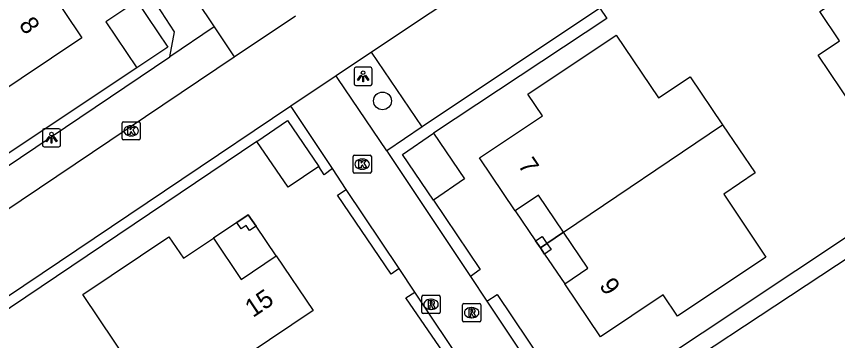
# Model space of a CAD drawing. Extents: x 158797 to 159887, y 384318 to 385255.
# Drawn here: x 159048.69 to 159093.85, y 384674.82 to 384692.68 of the extents above; entities that cross this region are included whole.
import ezdxf

# ---------------------------------------------------------------- set-up
doc = ezdxf.new("R2010")
doc.units = 0
for name, color, linetype in [('IMGEO_Boom', 7, 'Continuous'), ('IMGEO_Haag', 7, 'Continuous'), ('IMGEO_Kolk', 7, 'Continuous'), ('IMGEO_Lichtpunt', 7, 'Continuous'), ('IMGEO_Pand', 7, 'Continuous'), ('IMGEO_Pand_nummerreeks', 7, 'Continuous'), ('IMGEO_Pand_overbouw', 7, 'Continuous'), ('IMGEO_Parkeervlak_open', 7, 'Continuous'), ('IMGEO_Rijbaan_lokaal_open', 7, 'Continuous'), ('IMGEO_Rioolput', 7, 'Continuous'), ('IMGEO_Voetpad_open', 7, 'Continuous')]:
    doc.layers.add(name, color=color, linetype=linetype)

msp = doc.modelspace()

# ---------------------------------------------------------------- linework, layer by layer
at = {"layer": 'IMGEO_Boom'}
msp.add_circle((159068.824, 384688.021), 0.489, dxfattribs=at)
at = {"layer": 'IMGEO_Haag'}
for points in [[(159080.775, 384693.133), (159081.167, 384692.563), (159071.631, 384686.237)], [(159055.316, 384689.846), (159042.109, 384681.044)], [(159071.015, 384686.602), (159069.058, 384685.263)], [(159061.91, 384685.784), (159047.504, 384676.068), (159047.185, 384676.54)], [(159066.072, 384684.293), (159065.616, 384683.953), (159065.322, 384684.416)], [(159081.043, 384672.126), (159081.247, 384671.812), (159096.708, 384682.114), (159098.87, 384679.188), (159107.236, 384684.664), (159107.906, 384683.665)], [(159069.74, 384678.786), (159069.295, 384678.477), (159066.351, 384682.826), (159066.834, 384683.149)], [(159071.628, 384682.562), (159074.194, 384678.736), (159073.658, 384678.352)], [(159079.482, 384669.508), (159096.312, 384680.64), (159097.742, 384678.578)], [(159073.399, 384673.289), (159072.96, 384673.002), (159070.111, 384677.172), (159070.61, 384677.479)], [(159074.561, 384676.996), (159075.131, 384677.353), (159077.683, 384673.558)]]:
    msp.add_lwpolyline(points, dxfattribs=at)
at = {"layer": 'IMGEO_Kolk'}
for p, q in [((159054.503, 384685.948), (159054.503, 384686.8)), ((159054.578, 384686.874), (159055.43, 384686.874)), ((159054.991, 384686.654), (159055.016, 384686.654)), ((159055.504, 384686.8), (159055.504, 384685.948)), ((159055.014, 384686.094), (159054.989, 384686.094)), ((159055.43, 384685.874), (159054.578, 384685.874)), ((159067.211, 384684.108), (159067.211, 384684.96)), ((159067.286, 384685.034), (159068.138, 384685.034)), ((159067.699, 384684.814), (159067.724, 384684.814)), ((159068.212, 384684.96), (159068.212, 384684.108)), ((159068.138, 384684.034), (159067.286, 384684.034)), ((159067.722, 384684.254), (159067.697, 384684.254))]:
    msp.add_line(p, q, dxfattribs=at)
for points in [[(159054.503, 384685.948), (159054.503, 384686.8)], [(159054.578, 384686.874), (159055.43, 384686.874)], [(159054.824, 384686.574), (159054.947, 384686.574), (159054.947, 384686.423), (159055.077, 384686.574), (159055.241, 384686.574), (159055.095, 384686.423), (159055.248, 384686.174), (159055.096, 384686.174), (159055.011, 384686.338), (159054.947, 384686.271), (159054.947, 384686.174), (159054.824, 384686.174), (159054.824, 384686.574)], [(159055.504, 384686.8), (159055.504, 384685.948)], [(159055.43, 384685.874), (159054.578, 384685.874)], [(159067.211, 384684.108), (159067.211, 384684.96)], [(159067.286, 384685.034), (159068.138, 384685.034)], [(159067.532, 384684.734), (159067.655, 384684.734), (159067.655, 384684.583), (159067.785, 384684.734), (159067.949, 384684.734), (159067.803, 384684.583), (159067.956, 384684.334), (159067.804, 384684.334), (159067.719, 384684.498), (159067.655, 384684.431), (159067.655, 384684.334), (159067.532, 384684.334), (159067.532, 384684.734)], [(159068.212, 384684.96), (159068.212, 384684.108)], [(159068.138, 384684.034), (159067.286, 384684.034)]]:
    msp.add_lwpolyline(points, dxfattribs=at)
for centre, start, end in [((159054.58, 384686.798), 91.552, 178.448), ((159054.58, 384686.798), 91.552, 178.448), ((159055.428, 384686.798), 1.552, 88.448), ((159055.428, 384686.798), 1.552, 88.448), ((159054.58, 384685.95), 181.552, 268.448), ((159054.58, 384685.95), 181.552, 268.448), ((159055.428, 384685.95), 271.552, 358.448), ((159055.428, 384685.95), 271.552, 358.448), ((159067.288, 384684.958), 91.552, 178.448), ((159067.288, 384684.958), 91.552, 178.448), ((159068.136, 384684.958), 1.552, 88.448), ((159068.136, 384684.958), 1.552, 88.448), ((159067.288, 384684.11), 181.552, 268.448), ((159067.288, 384684.11), 181.552, 268.448), ((159068.136, 384684.11), 271.552, 358.448), ((159068.136, 384684.11), 271.552, 358.448)]:
    msp.add_arc(centre, 0.0765, start, end, dxfattribs=at)
for centre, major_axis, ratio, start_param, end_param in [((159054.99, 384686.374), (-0.387, 0.002), 0.722429, 4.712389, 7.853982), ((159055.015, 384686.374), (-0.39, 0.002), 0.717154, 1.570796, 4.712389), ((159067.698, 384684.534), (-0.387, 0.002), 0.722429, 4.712389, 7.853982), ((159067.723, 384684.534), (-0.39, 0.002), 0.717154, 1.570796, 4.712389)]:
    msp.add_ellipse(centre, major_axis=major_axis, ratio=ratio, start_param=start_param, end_param=end_param, dxfattribs=at)
at = {"layer": 'IMGEO_Lichtpunt'}
for p, q in [((159067.26, 384689.777), (159067.26, 384688.97)), ((159067.26, 384689.777), (159067.26, 384688.97)), ((159068.162, 384689.872), (159067.354, 384689.872)), ((159068.162, 384689.872), (159067.354, 384689.872)), ((159068.256, 384688.97), (159068.256, 384689.777)), ((159068.256, 384688.97), (159068.256, 384689.777)), ((159067.354, 384688.876), (159068.162, 384688.876)), ((159067.354, 384688.876), (159068.162, 384688.876)), ((159050.124, 384686.395), (159050.124, 384685.588)), ((159050.124, 384686.395), (159050.124, 384685.588)), ((159051.026, 384686.49), (159050.218, 384686.49)), ((159051.026, 384686.49), (159050.218, 384686.49)), ((159051.12, 384685.588), (159051.12, 384686.395)), ((159051.12, 384685.588), (159051.12, 384686.395)), ((159050.218, 384685.494), (159051.026, 384685.494)), ((159050.218, 384685.494), (159051.026, 384685.494))]:
    msp.add_line(p, q, dxfattribs=at)
for points in [[(159067.634, 384689.441), (159067.673, 384689.413), (159067.485, 384689.151), (159067.447, 384689.178), (159067.634, 384689.441)], [(159067.736, 384689.393), (159067.783, 384689.393), (159067.783, 384689.071), (159067.736, 384689.071), (159067.736, 384689.393)], [(159067.846, 384689.413), (159067.884, 384689.44), (159068.071, 384689.178), (159068.032, 384689.15), (159067.846, 384689.413)], [(159050.498, 384686.059), (159050.537, 384686.031), (159050.349, 384685.769), (159050.311, 384685.796), (159050.498, 384686.059)], [(159050.6, 384686.011), (159050.647, 384686.011), (159050.647, 384685.689), (159050.6, 384685.689), (159050.6, 384686.011)], [(159050.71, 384686.031), (159050.748, 384686.058), (159050.935, 384685.796), (159050.896, 384685.768), (159050.71, 384686.031)]]:
    msp.add_lwpolyline(points, dxfattribs=at)
for centre in [(159067.759, 384689.575), (159050.623, 384686.193)]:
    msp.add_circle(centre, 0.0994, dxfattribs=at)
for centre, start, end in [((159067.354, 384689.777), 90, 180), ((159067.354, 384689.777), 90, 180), ((159068.162, 384689.777), 0, 90), ((159068.162, 384689.777), 0, 90), ((159067.354, 384688.97), 180, 270), ((159067.354, 384688.97), 180, 270), ((159068.162, 384688.97), 270, 0), ((159068.162, 384688.97), 270, 360), ((159050.218, 384686.395), 90, 180), ((159050.218, 384686.395), 90, 180), ((159051.026, 384686.395), 0, 90), ((159051.026, 384686.395), 0, 90), ((159050.218, 384685.588), 180, 270), ((159050.218, 384685.588), 180, 270), ((159051.026, 384685.588), 270, 0), ((159051.026, 384685.588), 270, 360)]:
    msp.add_arc(centre, 0.0946, start, end, dxfattribs=at)
at = {"layer": 'IMGEO_Pand'}
for points in [[(159096.599, 384686.176), (159095.984, 384685.772), (159092.787, 384690.537), (159093.958, 384691.335), (159092.878, 384692.952), (159095.17, 384694.482), (159093.87, 384696.419), (159096.875, 384698.439), (159099.25, 384694.88)], [(159047.711, 384695.583), (159049.055, 384693.548), (159050.34, 384694.411), (159052.295, 384691.502), (159043.979, 384685.926), (159042.461, 384688.214), (159040.71, 384687.044), (159038.89, 384689.755)], [(159055.318, 384693.517), (159053.62, 384692.378), (159055.316, 384689.846)], [(159055.318, 384693.517), (159057.016, 384690.986), (159055.316, 384689.846)], [(159078.786, 384680.785), (159077.407, 384682.834), (159076.123, 384681.972), (159074.164, 384684.892), (159077.618, 384687.206), (159076.82, 384688.397), (159081.68, 384691.649), (159084.008, 384688.189), (159085.737, 384689.344), (159087.527, 384686.698)], [(159061.91, 384685.784), (159063.603, 384686.937), (159065.322, 384684.416)], [(159087.527, 384686.698), (159088.416, 384685.384), (159089.317, 384684.051), (159087.588, 384682.885), (159089.91, 384679.42), (159085.055, 384676.166), (159084.264, 384677.346), (159080.808, 384675.019), (159078.843, 384677.94), (159080.122, 384678.8), (159078.786, 384680.785)], [(159078.786, 384680.785), (159087.527, 384686.698)], [(159071.628, 384682.562), (159069.919, 384685.072), (159071.631, 384686.237)], [(159071.631, 384686.237), (159073.342, 384683.726), (159071.628, 384682.562)], [(159065.322, 384684.416), (159063.63, 384683.262), (159061.91, 384685.784)], [(159060.813, 384681.323), (159061.444, 384681.747), (159061.869, 384681.117), (159061.513, 384680.877), (159061.328, 384681.151), (159061.053, 384680.966), (159060.813, 384681.323)], [(159054.976, 384673.45), (159052.354, 384677.36), (159057.084, 384680.541), (159057.883, 384679.353), (159059.523, 384680.455), (159061.048, 384678.187), (159062.971, 384679.487), (159065.003, 384676.479), (159061.445, 384674.075)], [(159077.507, 384679.92), (159077.245, 384680.308), (159077.606, 384680.551), (159077.867, 384680.164)], [(159077.867, 384680.164), (159078.093, 384679.83), (159077.732, 384679.587), (159077.507, 384679.92)], [(159077.507, 384679.92), (159077.867, 384680.164)]]:
    msp.add_lwpolyline(points, dxfattribs=at)
at = {"layer": 'IMGEO_Pand_overbouw'}
for points in [[(159077.507, 384679.92), (159077.867, 384680.164), (159078.786, 384680.785), (159077.407, 384682.834), (159076.123, 384681.972), (159077.245, 384680.308)], [(159061.444, 384681.747), (159060.813, 384681.323), (159059.523, 384680.455), (159061.048, 384678.187), (159062.971, 384679.487), (159061.869, 384681.117)], [(159078.786, 384680.785), (159077.867, 384680.164), (159077.507, 384679.92), (159077.732, 384679.587), (159078.843, 384677.94), (159080.122, 384678.8)]]:
    msp.add_lwpolyline(points, close=True, dxfattribs=at)
at = {"layer": 'IMGEO_Parkeervlak_open'}
for points in [[(159080.775, 384693.133), (159071.015, 384686.602)], [(159071.015, 384686.602), (159068.226, 384690.7)]]:
    msp.add_lwpolyline(points, dxfattribs=at)
at = {"layer": 'IMGEO_Rijbaan_lokaal_open'}
for points in [[(159035.952, 384727.281), (159038.211, 384723.914), (159052.049, 384703.346), (159059.563, 384692.109)], [(159081.061, 384699.284), (159068.226, 384690.7)], [(159060.67, 384690.454), (159064.041, 384692.712)], [(159059.563, 384692.109), (159060.67, 384690.454)], [(159068.226, 384690.7), (159066.28, 384689.406)], [(159007.469, 384689.118), (159015.48, 384677.168), (159023.424, 384665.376), (159040.186, 384676.652), (159060.67, 384690.454)], [(159066.28, 384689.406), (159063.78, 384687.735)], [(159063.78, 384687.735), (159057.782, 384683.689), (159047.185, 384676.54)]]:
    msp.add_lwpolyline(points, dxfattribs=at)
at = {"layer": 'IMGEO_Rioolput'}
for p, q in [((159070.992, 384676.385), (159070.992, 384677.237)), ((159071.067, 384677.311), (159071.919, 384677.311)), ((159071.48, 384677.091), (159071.505, 384677.091)), ((159071.993, 384677.237), (159071.993, 384676.385)), ((159073.226, 384675.927), (159073.226, 384676.779)), ((159073.301, 384676.853), (159074.153, 384676.853)), ((159073.714, 384676.633), (159073.739, 384676.633)), ((159074.227, 384676.779), (159074.227, 384675.927)), ((159071.919, 384676.311), (159071.067, 384676.311)), ((159071.503, 384676.531), (159071.478, 384676.531)), ((159074.153, 384675.853), (159073.301, 384675.853)), ((159073.737, 384676.073), (159073.712, 384676.073))]:
    msp.add_line(p, q, dxfattribs=at)
for points in [[(159070.992, 384676.385), (159070.992, 384677.237)], [(159071.067, 384677.311), (159071.919, 384677.311)], [(159071.993, 384677.237), (159071.993, 384676.385)], [(159071.581, 384677.009), (159071.329, 384677.011), (159071.329, 384676.611)], [(159071.329, 384676.611), (159071.453, 384676.611), (159071.453, 384676.773), (159071.464, 384676.773)], [(159071.507, 384676.93), (159071.453, 384676.93), (159071.453, 384676.849)], [(159071.453, 384676.849), (159071.505, 384676.849)], [(159071.511, 384676.744), (159071.582, 384676.611), (159071.722, 384676.611), (159071.657, 384676.737)], [(159073.226, 384675.927), (159073.226, 384676.779)], [(159073.301, 384676.853), (159074.153, 384676.853)], [(159074.227, 384676.779), (159074.227, 384675.927)], [(159071.919, 384676.311), (159071.067, 384676.311)], [(159073.815, 384676.551), (159073.563, 384676.553), (159073.563, 384676.153)], [(159073.563, 384676.153), (159073.687, 384676.153), (159073.687, 384676.315), (159073.698, 384676.315)], [(159073.741, 384676.472), (159073.687, 384676.472), (159073.687, 384676.391)], [(159073.687, 384676.391), (159073.739, 384676.391)], [(159073.745, 384676.286), (159073.816, 384676.153), (159073.956, 384676.153), (159073.891, 384676.279)], [(159074.153, 384675.853), (159073.301, 384675.853)]]:
    msp.add_lwpolyline(points, dxfattribs=at)
for centre, radius, start, end in [((159071.069, 384677.235), 0.0765, 91.552, 178.448), ((159071.069, 384677.235), 0.0765, 91.552, 178.448), ((159071.917, 384677.235), 0.0765, 1.552, 88.448), ((159071.917, 384677.235), 0.0765, 1.552, 88.448), ((159071.463, 384676.72), 0.0533, 26.0293, 88.6989), ((159071.489, 384677.038), 0.19, 274.7715, 282.9687), ((159071.513, 384676.834), 0.0964, 77.0061, 93.1865), ((159071.527, 384676.891), 0.0378, 276.6634, 79.6772), ((159071.58, 384676.899), 0.109, 350.3612, 89.416), ((159071.578, 384676.899), 0.112, 277.5842, 350.9817), ((159071.562, 384676.684), 0.108, 29.5134, 73.7905), ((159073.303, 384676.777), 0.0765, 91.552, 178.448), ((159073.303, 384676.777), 0.0765, 91.552, 178.448), ((159074.151, 384676.777), 0.0765, 1.552, 88.448), ((159074.151, 384676.777), 0.0765, 1.552, 88.448), ((159071.069, 384676.387), 0.0765, 181.552, 268.448), ((159071.069, 384676.387), 0.0765, 181.552, 268.448), ((159071.917, 384676.387), 0.0765, 271.552, 358.448), ((159071.917, 384676.387), 0.0765, 271.552, 358.448), ((159073.697, 384676.262), 0.0533, 26.0293, 88.6989), ((159073.723, 384676.58), 0.19, 274.7715, 282.9687), ((159073.747, 384676.376), 0.0964, 77.0061, 93.1865), ((159073.761, 384676.433), 0.0378, 276.6634, 79.6772), ((159073.814, 384676.441), 0.109, 350.3612, 89.416), ((159073.812, 384676.441), 0.112, 277.5842, 350.9817), ((159073.796, 384676.226), 0.108, 29.5134, 73.7905), ((159073.303, 384675.929), 0.0765, 181.552, 268.448), ((159073.303, 384675.929), 0.0765, 181.552, 268.448), ((159074.151, 384675.929), 0.0765, 271.552, 358.448), ((159074.151, 384675.929), 0.0765, 271.552, 358.448)]:
    msp.add_arc(centre, radius, start, end, dxfattribs=at)
for centre, major_axis, ratio, start_param, end_param in [((159071.479, 384676.811), (-0.387, 0.002), 0.722429, 4.712389, 7.853982), ((159071.504, 384676.811), (-0.39, 0.002), 0.717154, 1.570796, 4.712389), ((159073.713, 384676.353), (-0.387, 0.002), 0.722429, 4.712389, 7.853982), ((159073.738, 384676.353), (-0.39, 0.002), 0.717154, 1.570796, 4.712389)]:
    msp.add_ellipse(centre, major_axis=major_axis, ratio=ratio, start_param=start_param, end_param=end_param, dxfattribs=at)
at = {"layer": 'IMGEO_Voetpad_open'}
for points in [[(159057.126, 384690.444), (159057.387, 384691.831), (159056.671, 384692.933), (159053.123, 384698.213)], [(159059.563, 384692.109), (159057.126, 384690.444)], [(159034.111, 384674.923), (159057.126, 384690.444)], [(159069.058, 384685.263), (159066.372, 384689.264), (159066.28, 384689.406)], [(159066.072, 384684.293), (159063.869, 384687.602), (159063.78, 384687.735)], [(159069.058, 384685.263), (159069.154, 384685.121), (159073.658, 384678.352)], [(159066.834, 384683.149), (159066.072, 384684.293)], [(159069.74, 384678.786), (159066.834, 384683.149)], [(159070.61, 384677.479), (159069.74, 384678.786)], [(159073.658, 384678.352), (159074.561, 384676.996)], [(159073.399, 384673.289), (159070.61, 384677.479)], [(159074.561, 384676.996), (159078.61, 384670.91), (159078.571, 384670.884)]]:
    msp.add_lwpolyline(points, dxfattribs=at)

# ---------------------------------------------------------------- texts
at = {"layer": 'IMGEO_Pand_nummerreeks'}
for s, rotation, p in [('8', 303.9017, (159048.798, 384692.223)), ('7', 303.8559, (159076.247, 384684.479)), ('9', 303.9304, (159080.713, 384677.848)), ('15', 34.0452, (159061.698, 384676.057))]:
    msp.add_text(s, height=1, rotation=rotation, dxfattribs=at).set_placement(p)

doc.saveas('drawing.dxf')
